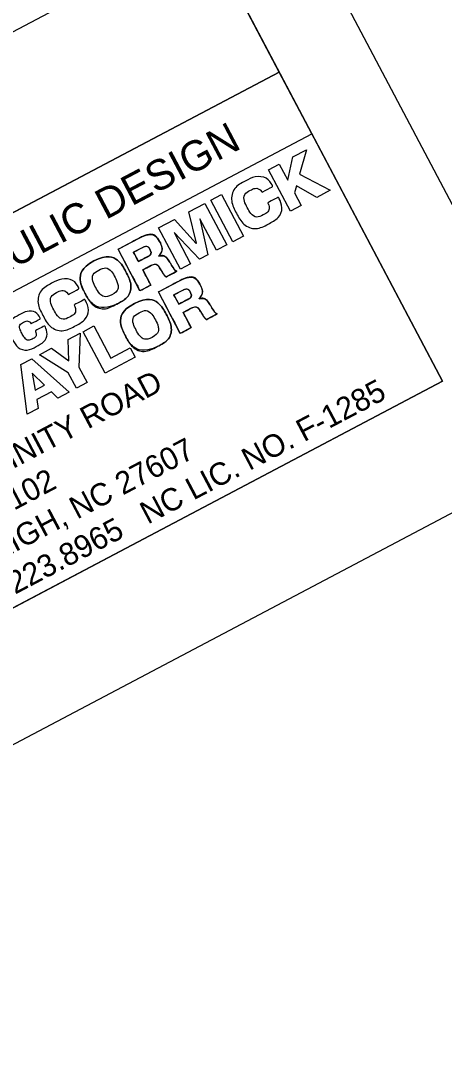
# Model space of a CAD drawing. Extents: x 1486990 to 1489232, y 497582 to 499336.
# Drawn here: x 1488946.8 to 1489025.8, y 498254 to 498447.2 of the extents above; entities that cross this region are included whole.
import ezdxf

# ---------------------------------------------------------------- set-up
doc = ezdxf.new("R2010")
doc.units = 0
for name, color, linetype in [('Prop Drainage Ditch Boundaries', 7, 'Continuous'), ('Prop Drainage Structure Catch Basin Open Throat 1 CELL', 7, 'Continuous'), ('Prop Drainage Structure Pipe Alternate 15in', 7, 'Continuous'), ('Prop Drainage Structure Plot Symbol 20 Scale', 7, 'Continuous'), ('Prop Earthen Structure V Ditch Berm Detail CELL', 7, 'Continuous')]:
    doc.layers.add(name, color=color, linetype=linetype)

msp = doc.modelspace()

# ---------------------------------------------------------------- linework, layer by layer
at = {"layer": 'Prop Drainage Ditch Boundaries'}
msp.add_lwpolyline([(1487562.23, 497581.96), (1489050.94, 498368.04), (1488539.66, 499336.34), (1487050.94, 498550.27)], close=True, dxfattribs=at)
at = {"layer": 'Prop Drainage Structure Catch Basin Open Throat 1 CELL'}
for points in [[(1488535.14, 499308.53), (1487208.67, 498608.12), (1487698.94, 497679.61), (1489025.4, 498380.01)], [(1487698.94, 497679.61), (1487208.66, 498608.09), (1488358.21, 499215.12), (1488428.29, 499082.43), (1488605.19, 499175.82), (1489025.4, 498380.01)]]:
    msp.add_lwpolyline(points, close=True, dxfattribs=at)
at = {"layer": 'Prop Drainage Structure Plot Symbol 20 Scale'}
msp.add_lwpolyline([(1487208.67, 498608.09), (1488222.08, 499143.23), (1488965.38, 498493.69), (1489025.4, 498380.01), (1487698.95, 497679.62)], close=True, dxfattribs=at)
at = {"layer": 'Prop Earthen Structure V Ditch Berm Detail CELL'}
for p, q in [((1488996.58, 498417.49), (1488997.56, 498421.8)), ((1488997.56, 498421.8), (1489000.06, 498423.12)), ((1489000.06, 498423.12), (1488998.81, 498418.57)), ((1488993.01, 498419.4), (1488995.02, 498420.46)), ((1488997.08, 498411.68), (1488993.01, 498419.4)), ((1488995.02, 498420.46), (1488996.58, 498417.49)), ((1488998.81, 498418.57), (1489004.49, 498415.59)), ((1488998.2, 498416.41), (1488997.84, 498415.12)), ((1489001.99, 498414.27), (1488998.2, 498416.41)), ((1489004.49, 498415.59), (1489001.99, 498414.27)), ((1488982.26, 498413.72), (1488984.27, 498414.78)), ((1488986.34, 498406), (1488982.26, 498413.72)), ((1488984.27, 498414.78), (1488988.35, 498407.06)), ((1488997.84, 498415.12), (1488999.1, 498412.74)), ((1488978.17, 498411.56), (1488981.13, 498413.13)), ((1488979.56, 498405.71), (1488978.17, 498411.56)), ((1488981.13, 498413.13), (1488985.21, 498405.41)), ((1488999.1, 498412.74), (1488997.08, 498411.68)), ((1488972.53, 498408.58), (1488975.49, 498410.15)), ((1488975.49, 498410.15), (1488979.54, 498405.7)), ((1488980.22, 498410.27), (1488980.2, 498410.26)), ((1488980.2, 498410.26), (1488981.68, 498403.54)), ((1488983.32, 498404.41), (1488980.22, 498410.27)), ((1488976.6, 498400.86), (1488972.53, 498408.58)), ((1488975.42, 498407.73), (1488975.4, 498407.72)), ((1488975.4, 498407.72), (1488978.5, 498401.86)), ((1488980.14, 498402.73), (1488975.42, 498407.73)), ((1488988.35, 498407.06), (1488986.34, 498406)), ((1488979.54, 498405.7), (1488979.56, 498405.71)), ((1488985.21, 498405.41), (1488983.32, 498404.41)), ((1488972.58, 498403.35), (1488972.59, 498403.33)), ((1488981.68, 498403.54), (1488980.14, 498402.73)), ((1488975.93, 498400.51), (1488973.94, 498399.46)), ((1488978.5, 498401.86), (1488976.6, 498400.86)), ((1488980.09, 498395.4), (1488980.1, 498395.38)), ((1488983.45, 498392.56), (1488981.46, 498391.51)), ((1488958.48, 498389.24), (1488960.49, 498390.31)), ((1488960.49, 498390.31), (1488963.65, 498384.32)), ((1488955.66, 498387.76), (1488957.94, 498388.96)), ((1488957.94, 498388.96), (1488957.69, 498382.64)), ((1488962.55, 498381.52), (1488958.48, 498389.24)), ((1488955.78, 498383.81), (1488955.66, 498387.76)), ((1488950.31, 498384.93), (1488952.59, 498386.14)), ((1488955.68, 498381.57), (1488950.31, 498384.93)), ((1488952.59, 498386.14), (1488955.78, 498383.81)), ((1488963.65, 498384.32), (1488967.25, 498386.22)), ((1488967.25, 498386.22), (1488968.16, 498384.49)), ((1488946.85, 498383.1), (1488948.89, 498384.18)), ((1488948.04, 498373.86), (1488946.85, 498383.1)), ((1488948.89, 498384.18), (1488955.85, 498377.99)), ((1488957.69, 498382.64), (1488959.21, 498379.76)), ((1488968.16, 498384.49), (1488962.55, 498381.52)), ((1488949, 498381.51), (1488948.98, 498381.49)), ((1488948.98, 498381.49), (1488949.53, 498378.33)), ((1488951.29, 498379.25), (1488949, 498381.51)), ((1488957.2, 498378.7), (1488955.68, 498381.57)), ((1488949.53, 498378.33), (1488951.29, 498379.25)), ((1488959.21, 498379.76), (1488957.2, 498378.7)), ((1488952.55, 498378.01), (1488949.86, 498376.59)), ((1488953.76, 498376.88), (1488952.55, 498378.01)), ((1488955.85, 498377.99), (1488953.76, 498376.88)), ((1488950.1, 498374.95), (1488948.04, 498373.86)), ((1488949.86, 498376.59), (1488950.1, 498374.95))]:
    msp.add_line(p, q, dxfattribs=at)
for points in [[(1488709.02, 498286.64), (1488994.97, 498437.63), (1488981.06, 498463.98), (1488695.11, 498312.99)], [(1488911.45, 498378.78), (1489001.06, 498426.1), (1488994.97, 498437.63), (1488905.36, 498390.32)], [(1488911.45, 498378.78), (1489001.06, 498426.1), (1489025.4, 498380.01), (1488935.79, 498332.69)]]:
    msp.add_lwpolyline(points, close=True, dxfattribs=at)
for points in [[(1488993.01, 498419.4), (1488995.02, 498420.46), (1488996.58, 498417.49), (1488997.56, 498421.8), (1489000.06, 498423.12), (1488998.81, 498418.57), (1489004.49, 498415.59), (1489001.99, 498414.27), (1488998.2, 498416.41), (1488997.84, 498415.12), (1488999.1, 498412.74), (1488997.08, 498411.68), (1488993.01, 498419.4)], [(1488982.26, 498413.72), (1488984.27, 498414.78), (1488988.35, 498407.06), (1488986.34, 498406), (1488982.26, 498413.72)], [(1488972.53, 498408.58), (1488975.49, 498410.15), (1488979.54, 498405.7), (1488979.56, 498405.71), (1488978.17, 498411.56), (1488981.13, 498413.13), (1488985.21, 498405.41), (1488983.32, 498404.41), (1488980.22, 498410.27), (1488980.2, 498410.26), (1488981.68, 498403.54), (1488980.14, 498402.73), (1488975.42, 498407.73), (1488975.4, 498407.72), (1488978.5, 498401.86), (1488976.6, 498400.86), (1488972.53, 498408.58)], [(1488971.11, 498401.55), (1488969.58, 498400.75), (1488971.07, 498397.94), (1488969.06, 498396.88), (1488964.98, 498404.6), (1488968.92, 498406.67)], [(1488969.44, 498404.89), (1488967.84, 498404.05), (1488968.76, 498402.31), (1488970.45, 498403.2)], [(1488978.62, 498393.61), (1488977.1, 498392.8), (1488978.58, 498389.99), (1488976.57, 498388.93), (1488972.5, 498396.65), (1488976.43, 498398.73)], [(1488976.96, 498396.94), (1488975.36, 498396.1), (1488976.28, 498394.36), (1488977.96, 498395.25)], [(1488958.48, 498389.24), (1488960.49, 498390.31), (1488963.65, 498384.32), (1488967.25, 498386.22), (1488968.16, 498384.49), (1488962.55, 498381.52), (1488958.48, 498389.24)], [(1488957.69, 498382.64), (1488959.21, 498379.76), (1488957.2, 498378.7), (1488955.68, 498381.57), (1488950.31, 498384.93), (1488952.59, 498386.14), (1488955.78, 498383.81), (1488955.66, 498387.76), (1488957.94, 498388.96), (1488957.69, 498382.64)], [(1488946.85, 498383.1), (1488948.89, 498384.18), (1488955.85, 498377.99), (1488953.76, 498376.88), (1488952.55, 498378.01), (1488949.86, 498376.59), (1488950.1, 498374.95), (1488948.04, 498373.86), (1488946.85, 498383.1)], [(1488949.53, 498378.33), (1488951.29, 498379.25), (1488949, 498381.51), (1488948.98, 498381.49), (1488949.53, 498378.33)]]:
    msp.add_lwpolyline(points, dxfattribs=at)
for points in [[(1488991.81, 498415.24), (1488991.29, 498415.96), (1488990.47, 498416.05), (1488989.63, 498415.61), (1488988.33, 498414.92), (1488988.44, 498413.51), (1488989.04, 498412.37), (1488989.65, 498411.22), (1488990.75, 498410.34), (1488992.05, 498411.02), (1488992.99, 498411.52), (1488993.25, 498412.34), (1488992.85, 498413.27), (1488992.85, 498413.27), (1488994.86, 498414.33), (1488994.86, 498414.33), (1488995.81, 498412.29), (1488994.96, 498410.35), (1488993.01, 498409.31), (1488990.67, 498408.08), (1488988.22, 498409.07), (1488987.03, 498411.3), (1488985.85, 498413.54), (1488986.42, 498416.13), (1488988.76, 498417.36), (1488990.42, 498418.24), (1488992.79, 498418.13), (1488993.83, 498416.3), (1488993.83, 498416.3), (1488991.81, 498415.24), (1488991.81, 498415.24)], [(1488991.81, 498415.24), (1488991.29, 498415.96), (1488990.47, 498416.05), (1488989.63, 498415.61), (1488988.33, 498414.92), (1488988.44, 498413.51), (1488989.04, 498412.37), (1488989.65, 498411.22), (1488990.75, 498410.34), (1488992.05, 498411.02), (1488992.99, 498411.52), (1488993.25, 498412.34), (1488992.85, 498413.27), (1488992.85, 498413.27), (1488994.86, 498414.33), (1488994.86, 498414.33), (1488995.81, 498412.29), (1488994.96, 498410.35), (1488993.01, 498409.31), (1488990.67, 498408.08), (1488988.22, 498409.07), (1488987.03, 498411.3), (1488985.85, 498413.54), (1488986.42, 498416.13), (1488988.76, 498417.36), (1488990.42, 498418.24), (1488992.79, 498418.13), (1488993.83, 498416.3), (1488993.83, 498416.3), (1488991.81, 498415.24), (1488991.81, 498415.24)], [(1488964.98, 498404.6), (1488964.98, 498404.6), (1488968.92, 498406.67), (1488968.92, 498406.67), (1488970.28, 498407.39), (1488971.94, 498407.49), (1488972.77, 498405.93), (1488973.21, 498405.1), (1488973.22, 498404.1), (1488972.58, 498403.35), (1488972.58, 498403.35), (1488972.59, 498403.33), (1488972.59, 498403.33), (1488973.51, 498403.57), (1488974.24, 498402.78), (1488974.69, 498402.08), (1488974.88, 498401.76), (1488975.51, 498400.65), (1488975.93, 498400.51), (1488975.93, 498400.51), (1488973.94, 498399.46), (1488973.94, 498399.46), (1488973.63, 498399.62), (1488973.2, 498400.36), (1488973.07, 498400.57), (1488972.6, 498401.32), (1488972.05, 498402.05), (1488971.11, 498401.55), (1488971.11, 498401.55), (1488969.58, 498400.75), (1488969.58, 498400.75), (1488969.58, 498400.75), (1488971.07, 498397.94), (1488971.07, 498397.94), (1488971.07, 498397.94), (1488969.06, 498396.88), (1488969.06, 498396.88), (1488969.06, 498396.88), (1488964.98, 498404.6), (1488964.98, 498404.6)], [(1488968.92, 498406.67), (1488970.28, 498407.39), (1488971.94, 498407.49), (1488972.77, 498405.93), (1488973.21, 498405.1), (1488973.22, 498404.1), (1488972.58, 498403.35)], [(1488968.76, 498402.31), (1488968.76, 498402.31), (1488970.45, 498403.2), (1488970.45, 498403.2), (1488971.05, 498403.52), (1488971.21, 498404.01), (1488970.9, 498404.6), (1488970.6, 498405.17), (1488970, 498405.19), (1488969.44, 498404.89), (1488969.44, 498404.89), (1488967.84, 498404.05), (1488967.84, 498404.05), (1488967.84, 498404.05), (1488968.76, 498402.31), (1488968.76, 498402.31)], [(1488970.45, 498403.2), (1488971.05, 498403.52), (1488971.21, 498404.01), (1488970.9, 498404.6), (1488970.6, 498405.17), (1488970, 498405.19), (1488969.44, 498404.89)], [(1488960.49, 498402.43), (1488962.92, 498403.72), (1488965.24, 498402.66), (1488966.42, 498400.42), (1488967.6, 498398.18), (1488967.17, 498395.67), (1488964.74, 498394.39), (1488962.31, 498393.1), (1488959.99, 498394.16), (1488958.81, 498396.4), (1488957.63, 498398.64), (1488958.06, 498401.15), (1488960.49, 498402.43)], [(1488963.75, 498393.99), (1488961.69, 498393.42), (1488959.83, 498394.47), (1488958.81, 498396.4), (1488957.63, 498398.64), (1488958.06, 498401.15), (1488960.49, 498402.43)], [(1488960.49, 498402.43), (1488962.92, 498403.72), (1488965.24, 498402.66), (1488966.42, 498400.42), (1488967.6, 498398.18), (1488967.17, 498395.67), (1488964.74, 498394.39), (1488964.41, 498394.21), (1488964.08, 498394.08), (1488963.75, 498393.99)], [(1488973.94, 498399.46), (1488973.63, 498399.62), (1488973.2, 498400.36), (1488973.07, 498400.57), (1488972.6, 498401.32), (1488972.05, 498402.05), (1488971.11, 498401.55)], [(1488972.59, 498403.33), (1488973.51, 498403.57), (1488974.24, 498402.78), (1488974.69, 498402.08), (1488974.88, 498401.76), (1488975.51, 498400.65), (1488975.93, 498400.51)], [(1488963.83, 498396.12), (1488965.12, 498396.8), (1488965.02, 498398.21), (1488964.41, 498399.36), (1488963.81, 498400.51), (1488962.7, 498401.39), (1488961.41, 498400.7), (1488960.11, 498400.02), (1488960.22, 498398.61), (1488960.82, 498397.46), (1488961.43, 498396.32), (1488962.53, 498395.43), (1488963.83, 498396.12)], [(1488963.83, 498396.12), (1488965.12, 498396.8), (1488965.02, 498398.21), (1488964.41, 498399.36), (1488963.81, 498400.51), (1488962.7, 498401.39), (1488961.41, 498400.7), (1488960.11, 498400.02), (1488960.22, 498398.61), (1488960.82, 498397.46), (1488961.43, 498396.32), (1488962.53, 498395.43), (1488963.83, 498396.12)], [(1488955.75, 498396.2), (1488955.23, 498396.92), (1488954.41, 498397.01), (1488953.57, 498396.56), (1488952.27, 498395.88), (1488952.38, 498394.47), (1488952.98, 498393.32), (1488953.59, 498392.18), (1488954.69, 498391.29), (1488955.99, 498391.98), (1488956.93, 498392.48), (1488957.18, 498393.3), (1488956.79, 498394.23), (1488956.79, 498394.23), (1488958.8, 498395.29), (1488958.8, 498395.29), (1488959.74, 498393.24), (1488958.9, 498391.31), (1488956.94, 498390.27), (1488954.61, 498389.04), (1488952.15, 498390.02), (1488950.97, 498392.26), (1488949.79, 498394.5), (1488950.36, 498397.08), (1488952.7, 498398.32), (1488954.36, 498399.2), (1488956.73, 498399.09), (1488957.76, 498397.26), (1488957.76, 498397.26), (1488955.75, 498396.2), (1488955.75, 498396.2)], [(1488955.75, 498396.2), (1488955.23, 498396.92), (1488954.41, 498397.01), (1488953.57, 498396.56), (1488952.27, 498395.88), (1488952.38, 498394.47), (1488952.98, 498393.32), (1488953.59, 498392.18), (1488954.69, 498391.29), (1488955.99, 498391.98), (1488956.93, 498392.48), (1488957.18, 498393.3), (1488956.79, 498394.23), (1488956.79, 498394.23), (1488958.8, 498395.29), (1488958.8, 498395.29), (1488959.74, 498393.24), (1488958.9, 498391.31), (1488956.94, 498390.27), (1488954.61, 498389.04), (1488952.15, 498390.02), (1488950.97, 498392.26), (1488949.79, 498394.5), (1488950.36, 498397.08), (1488952.7, 498398.32), (1488954.36, 498399.2), (1488956.73, 498399.09), (1488957.76, 498397.26), (1488957.76, 498397.26), (1488955.75, 498396.2), (1488955.75, 498396.2)], [(1488972.5, 498396.65), (1488972.5, 498396.65), (1488976.43, 498398.73), (1488976.43, 498398.73), (1488977.79, 498399.44), (1488979.46, 498399.54), (1488980.28, 498397.98), (1488980.72, 498397.15), (1488980.74, 498396.15), (1488980.09, 498395.4), (1488980.09, 498395.4), (1488980.1, 498395.38), (1488980.1, 498395.38), (1488981.03, 498395.62), (1488981.75, 498394.83), (1488982.2, 498394.13), (1488982.4, 498393.81), (1488983.03, 498392.7), (1488983.45, 498392.56), (1488983.45, 498392.56), (1488981.46, 498391.51), (1488981.46, 498391.51), (1488981.15, 498391.68), (1488980.72, 498392.42), (1488980.58, 498392.62), (1488980.12, 498393.37), (1488979.56, 498394.1), (1488978.62, 498393.61), (1488978.62, 498393.61), (1488977.1, 498392.8), (1488977.1, 498392.8), (1488977.1, 498392.8), (1488978.58, 498389.99), (1488978.58, 498389.99), (1488978.58, 498389.99), (1488976.57, 498388.93), (1488976.57, 498388.93), (1488976.57, 498388.93), (1488972.5, 498396.65), (1488972.5, 498396.65)], [(1488976.43, 498398.73), (1488977.79, 498399.44), (1488979.46, 498399.54), (1488980.28, 498397.98), (1488980.72, 498397.15), (1488980.74, 498396.15), (1488980.09, 498395.4)], [(1488976.28, 498394.36), (1488976.28, 498394.36), (1488977.96, 498395.25), (1488977.96, 498395.25), (1488978.57, 498395.57), (1488978.72, 498396.06), (1488978.41, 498396.65), (1488978.11, 498397.22), (1488977.52, 498397.24), (1488976.96, 498396.94), (1488976.96, 498396.94), (1488975.36, 498396.1), (1488975.36, 498396.1), (1488975.36, 498396.1), (1488976.28, 498394.36), (1488976.28, 498394.36)], [(1488977.96, 498395.25), (1488978.57, 498395.57), (1488978.72, 498396.06), (1488978.41, 498396.65), (1488978.11, 498397.22), (1488977.52, 498397.24), (1488976.96, 498396.94)], [(1488968.02, 498394.49), (1488970.45, 498395.77), (1488972.77, 498394.72), (1488973.95, 498392.48), (1488975.13, 498390.24), (1488974.7, 498387.73), (1488972.26, 498386.45), (1488969.83, 498385.16), (1488967.52, 498386.22), (1488966.33, 498388.46), (1488965.15, 498390.7), (1488965.58, 498393.21), (1488968.02, 498394.49)], [(1488971.27, 498386.05), (1488969.22, 498385.47), (1488967.36, 498386.53), (1488966.33, 498388.46), (1488965.15, 498390.7), (1488965.58, 498393.21), (1488968.02, 498394.49)], [(1488968.02, 498394.49), (1488970.45, 498395.77), (1488972.77, 498394.72), (1488973.95, 498392.48), (1488975.13, 498390.24), (1488974.7, 498387.73), (1488972.26, 498386.45), (1488971.93, 498386.27), (1488971.6, 498386.14), (1488971.27, 498386.05)], [(1488980.1, 498395.38), (1488981.03, 498395.62), (1488981.75, 498394.83), (1488982.2, 498394.13), (1488982.4, 498393.81), (1488983.03, 498392.7), (1488983.45, 498392.56)], [(1488948.78, 498390.72), (1488948.52, 498391.19), (1488947.92, 498391.3), (1488947.46, 498391.06), (1488946.43, 498390.51), (1488946.73, 498389.55), (1488947.14, 498388.77), (1488947.52, 498388.05), (1488948.23, 498387.47), (1488949.01, 498387.88), (1488949.65, 498388.22), (1488949.78, 498388.76), (1488949.55, 498389.4), (1488949.55, 498389.4), (1488951.33, 498390.34), (1488951.33, 498390.34), (1488951.96, 498388.75), (1488951.25, 498387.27), (1488949.76, 498386.48), (1488948.07, 498385.59), (1488946.21, 498386.08), (1488945.3, 498387.8), (1488944.36, 498389.59), (1488944.82, 498391.46), (1488946.63, 498392.42), (1488948.02, 498393.15), (1488949.65, 498393.07), (1488950.56, 498391.66), (1488950.56, 498391.66), (1488948.78, 498390.72), (1488948.78, 498390.72)], [(1488948.78, 498390.72), (1488948.52, 498391.19), (1488947.92, 498391.3), (1488947.46, 498391.06), (1488946.43, 498390.51), (1488946.73, 498389.55), (1488947.14, 498388.77), (1488947.52, 498388.05), (1488948.23, 498387.47), (1488949.01, 498387.88), (1488949.65, 498388.22), (1488949.78, 498388.76), (1488949.55, 498389.4), (1488949.55, 498389.4), (1488951.33, 498390.34), (1488951.33, 498390.34), (1488951.96, 498388.75), (1488951.25, 498387.27), (1488949.76, 498386.48), (1488948.07, 498385.59), (1488946.21, 498386.08), (1488945.3, 498387.8), (1488944.36, 498389.59), (1488944.82, 498391.46), (1488946.63, 498392.42), (1488948.02, 498393.15), (1488949.65, 498393.07), (1488950.56, 498391.66), (1488950.56, 498391.66), (1488948.78, 498390.72), (1488948.78, 498390.72)], [(1488971.35, 498388.18), (1488972.65, 498388.86), (1488972.54, 498390.27), (1488971.94, 498391.42), (1488971.33, 498392.56), (1488970.23, 498393.44), (1488968.93, 498392.76), (1488967.63, 498392.07), (1488967.74, 498390.67), (1488968.35, 498389.52), (1488968.95, 498388.37), (1488970.05, 498387.49), (1488971.35, 498388.18)], [(1488971.35, 498388.18), (1488972.65, 498388.86), (1488972.54, 498390.27), (1488971.94, 498391.42), (1488971.33, 498392.56), (1488970.23, 498393.44), (1488968.93, 498392.76), (1488967.63, 498392.07), (1488967.74, 498390.67), (1488968.35, 498389.52), (1488968.95, 498388.37), (1488970.05, 498387.49), (1488971.35, 498388.18)], [(1488981.46, 498391.51), (1488981.15, 498391.68), (1488980.72, 498392.42), (1488980.58, 498392.62), (1488980.12, 498393.37), (1488979.56, 498394.1), (1488978.62, 498393.61)]]:
    msp.add_open_spline(points, degree=3, dxfattribs=at)

# ---------------------------------------------------------------- texts
at = {"layer": 'Prop Drainage Structure Pipe Alternate 15in'}
msp.add_text('HYDRAULIC DESIGN', height=5.625, rotation=27.8351, dxfattribs=at).set_placement((1488922.4, 498388.76))
at = {"layer": 'Prop Earthen Structure V Ditch Berm Detail CELL'}
for s, height, p in [('5400 TRINITY ROAD', 4.1773, (1488926.41, 498353.61)), ('919.223.8965   NC LIC. NO. F-1285', 4.1773, (1488936.17, 498335.14)), ('RALEIGH, NC 27607', 4.1773, (1488932.91, 498341.3)), ('SUITE 102', 4.177, (1488929.66, 498347.46))]:
    msp.add_text(s, height=height, rotation=27.8351, dxfattribs=at).set_placement(p)

doc.saveas('drawing.dxf')
